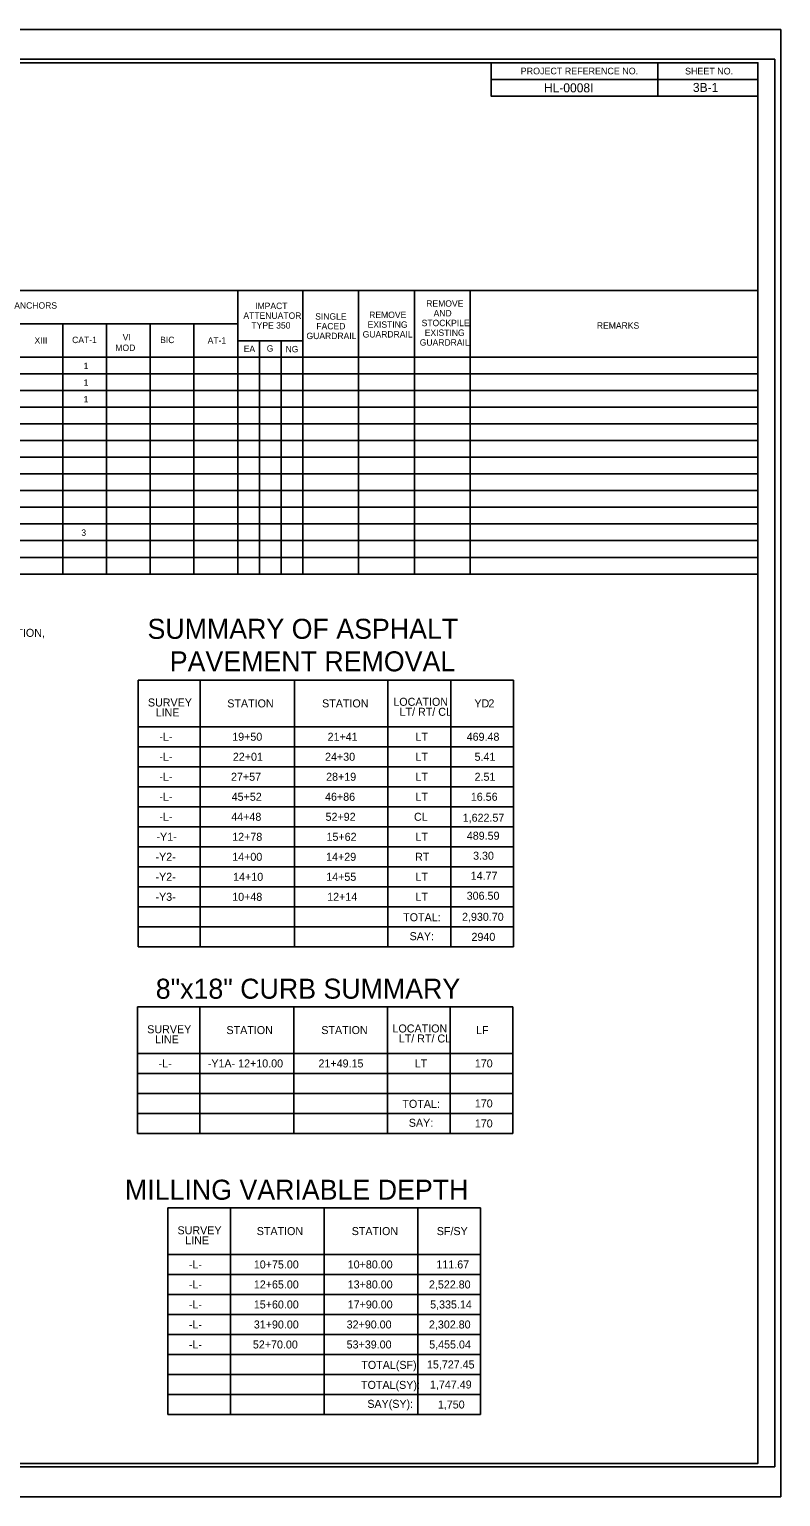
# Model space of a CAD drawing. Extents: x 4059498 to 4061182, y -2958297 to -2957197.
# Drawn here: x 4060619 to 4061182, y -2958297 to -2957197 of the extents above; entities that cross this region are included whole.
import ezdxf

# ---------------------------------------------------------------- set-up
doc = ezdxf.new("R2010")
doc.units = 0
for name, color, linetype in [('Sheet Data Field CELL', 7, 'Continuous'), ('Sheet Plot Border Inside CELL', 7, 'Continuous'), ('Sheet Plot Border Outside CELL', 7, 'Continuous'), ('Sheet Summary Combination CELL', 7, 'Continuous'), ('Sheet Summary Combination Grid CELL', 7, 'Continuous')]:
    doc.layers.add(name, color=color, linetype=linetype)

msp = doc.modelspace()

# ---------------------------------------------------------------- linework, layer by layer
at = {"layer": 'Sheet Plot Border Inside CELL'}
msp.add_lwpolyline([(4061178, -2957219.4), (4059511.5, -2957219.4), (4059511.5, -2958274.5), (4061178, -2958274.5)], close=True, dxfattribs=at)
at = {"layer": 'Sheet Plot Border Outside CELL'}
msp.add_lwpolyline([(4061182.5, -2957197), (4059498.5, -2957197), (4059498.5, -2958297), (4061182.5, -2958297)], close=True, dxfattribs=at)
at = {"layer": 'Sheet Summary Combination CELL'}
for p, q in [((4061090.5, -2957222), (4061090.5, -2957247)), ((4060965.4, -2957234.5), (4061165.5, -2957234.5)), ((4060965.4, -2957247), (4061165.5, -2957247)), ((4060842.1, -2957684.8), (4060842.1, -2957684.8)), ((4060848.3, -2957684.9), (4060848.3, -2957684.9)), ((4060857.4, -2957684.7), (4060857.4, -2957684.7)), ((4060863, -2957684.8), (4060863, -2957684.8)), ((4060841.5, -2957929.8), (4060841.5, -2957929.8)), ((4060847.7, -2957929.9), (4060847.7, -2957929.9)), ((4060856.8, -2957929.7), (4060856.8, -2957929.7)), ((4060862.4, -2957929.8), (4060862.4, -2957929.8)), ((4060864.2, -2958080.5), (4060864.2, -2958080.5)), ((4060870.5, -2958080.6), (4060870.5, -2958080.6)), ((4060879.5, -2958080.4), (4060879.5, -2958080.4)), ((4060885.1, -2958080.5), (4060885.1, -2958080.5))]:
    msp.add_line(p, q, dxfattribs=at)
for points in [[(4061165.5, -2957222), (4059665.5, -2957222), (4059665.5, -2958272), (4061165.5, -2958272)], [(4060965.4, -2957222), (4061165.5, -2957222), (4061165.5, -2957247), (4060965.4, -2957247)]]:
    msp.add_lwpolyline(points, close=True, dxfattribs=at)
at = {"layer": 'Sheet Summary Combination Grid CELL'}
for p, q in [((4059665.5, -2957392.8), (4061165.5, -2957392.8)), ((4060775.4, -2957392.8), (4060775.4, -2957605.3)), ((4060824.3, -2957392.8), (4060824.3, -2957605.3)), ((4060866.1, -2957392.8), (4060866.1, -2957605.3)), ((4060907.9, -2957392.8), (4060907.9, -2957605.3)), ((4060949.7, -2957392.8), (4060949.7, -2957605.3)), ((4060775.4, -2957417.8), (4060298.3, -2957417.8)), ((4060644.2, -2957417.8), (4060644.2, -2957605.3)), ((4060677, -2957417.8), (4060677, -2957605.3)), ((4060709.8, -2957417.8), (4060709.8, -2957605.3)), ((4060742.6, -2957417.8), (4060742.6, -2957605.3)), ((4060775.4, -2957430.5), (4060824, -2957430.5)), ((4060791.7, -2957430.5), (4060791.8, -2957605.3)), ((4060808, -2957430.5), (4060808.1, -2957605.3)), ((4059665.5, -2957442.8), (4061165.5, -2957442.8)), ((4059665.5, -2957455.3), (4061165.5, -2957455.3)), ((4059665.5, -2957467.8), (4061165.5, -2957467.8)), ((4059665.5, -2957480.3), (4061165.5, -2957480.3)), ((4059665.5, -2957492.8), (4061165.5, -2957492.8)), ((4059665.5, -2957505.3), (4061165.5, -2957505.3)), ((4059665.5, -2957517.8), (4061165.5, -2957517.8)), ((4059665.5, -2957530.3), (4061165.5, -2957530.3)), ((4059665.5, -2957542.8), (4061165.5, -2957542.8)), ((4059665.5, -2957555.3), (4061165.5, -2957555.3)), ((4059665.5, -2957567.8), (4061165.5, -2957567.8)), ((4059665.5, -2957580.3), (4061165.5, -2957580.3)), ((4059665.5, -2957592.8), (4061165.5, -2957592.8)), ((4059665.5, -2957605.3), (4061165.5, -2957605.3)), ((4060700.8, -2957684.8), (4060982.2, -2957684.8)), ((4060700.8, -2957684.8), (4060700.8, -2957884.8)), ((4060747.4, -2957684.8), (4060747.4, -2957884.8)), ((4060818.1, -2957684.8), (4060818.1, -2957884.8)), ((4060888.1, -2957684.8), (4060888.1, -2957884.8)), ((4060935.3, -2957684.8), (4060935.3, -2957884.8)), ((4060982.2, -2957684.8), (4060982.2, -2957884.8)), ((4060700.8, -2957719.8), (4060982.2, -2957719.8)), ((4060700.8, -2957734.8), (4060982.2, -2957734.8)), ((4060700.8, -2957749.8), (4060982.2, -2957749.8)), ((4060700.8, -2957764.8), (4060982.2, -2957764.8)), ((4060982.2, -2957764.8), (4060982.2, -2957884.8)), ((4060700.8, -2957779.8), (4060982.2, -2957779.8)), ((4060700.8, -2957794.8), (4060982.2, -2957794.8)), ((4060700.8, -2957794.8), (4060982.2, -2957794.8)), ((4060700.8, -2957809.8), (4060982.2, -2957809.8)), ((4060700.8, -2957824.8), (4060982.2, -2957824.8)), ((4060700.8, -2957839.8), (4060982.2, -2957839.8)), ((4060700.8, -2957854.8), (4060982.2, -2957854.8)), ((4060700.8, -2957869.8), (4060982.2, -2957869.8)), ((4060700.8, -2957884.8), (4060982.2, -2957884.8)), ((4060700.2, -2957929.7), (4060981.6, -2957929.7)), ((4060700.2, -2957929.7), (4060700.2, -2958024.7)), ((4060747.1, -2957929.7), (4060747.1, -2958024.7)), ((4060817.5, -2957929.7), (4060817.5, -2958024.7)), ((4060887.8, -2957929.7), (4060887.8, -2958024.7)), ((4060934.7, -2957929.7), (4060934.7, -2958024.7)), ((4060981.6, -2957929.7), (4060981.6, -2958024.7)), ((4060700.2, -2957964.7), (4060981.6, -2957964.7)), ((4060700.2, -2957979.7), (4060981.6, -2957979.7)), ((4060700.2, -2957994.7), (4060981.6, -2957994.7)), ((4060700.2, -2957994.7), (4060981.6, -2957994.7)), ((4060700.2, -2958009.7), (4060981.6, -2958009.7)), ((4060700.2, -2958024.7), (4060981.6, -2958024.7)), ((4060723, -2958080.4), (4060957.4, -2958080.4)), ((4060723, -2958080.4), (4060723, -2958235.4)), ((4060769.9, -2958080.4), (4060769.9, -2958235.4)), ((4060840.2, -2958080.4), (4060840.2, -2958235.4)), ((4060910.5, -2958080.4), (4060910.5, -2958235.4)), ((4060957.4, -2958080.4), (4060957.4, -2958235.4)), ((4060723, -2958115.4), (4060957.4, -2958115.4)), ((4060723, -2958130.4), (4060957.4, -2958130.4)), ((4060723, -2958145.4), (4060957.4, -2958145.4)), ((4060723, -2958145.4), (4060957.4, -2958145.4)), ((4060723, -2958160.4), (4060957.4, -2958160.4)), ((4060723, -2958160.4), (4060957.4, -2958160.4)), ((4060723, -2958175.4), (4060957.4, -2958175.4)), ((4060723, -2958175.4), (4060957.4, -2958175.4)), ((4060723, -2958190.4), (4060957.4, -2958190.4)), ((4060723, -2958190.4), (4060957.4, -2958190.4)), ((4060723, -2958205.4), (4060957.4, -2958205.4)), ((4060723, -2958205.4), (4060957.4, -2958205.4)), ((4060723, -2958220.4), (4060957.4, -2958220.4)), ((4060723, -2958235.4), (4060957.4, -2958235.4))]:
    msp.add_line(p, q, dxfattribs=at)

# ---------------------------------------------------------------- texts
at = {"layer": 'Sheet Data Field CELL'}
for s, p in [('HL-0008I', (4061005, -2957244.2)), ('3B-1', (4061116.7, -2957243.9))]:
    msp.add_text(s, height=6.75, dxfattribs=at).set_placement(p)
at = {"layer": 'Sheet Summary Combination CELL'}
for s, height, p in [('PROJECT REFERENCE NO.', 5, (4060987.6, -2957230.7)), ('SHEET NO.', 5, (4061110.8, -2957230.8)), ('ANCHORS', 4.8, (4060607.9, -2957406.4)), ('IMPACT', 4.8, (4060788.5, -2957406.7)), ('REMOVE', 4.8, (4060916.8, -2957404.9)), ('ATTENUATOR', 4.8, (4060779.7, -2957414)), ('SINGLE', 4.8, (4060833.5, -2957414.6)), ('EXISTING', 4.8, (4060872.8, -2957420.7)), ('REMOVE', 4.8, (4060874, -2957413.4)), ('STOCKPILE', 4.8, (4060913.3, -2957419.5)), ('AND', 4.8, (4060922.3, -2957412.2)), ('VI', 4.8, (4060689.2, -2957430.2)), ('TYPE 350', 4.8, (4060785.7, -2957421.3)), ('GUARDRAIL', 4.8, (4060827, -2957429.2)), ('FACED', 4.8, (4060834.4, -2957421.9)), ('GUARDRAIL', 4.8, (4060869.1, -2957428)), ('EXISTING', 4.8, (4060915.6, -2957426.8)), ('REMARKS', 4.8, (4061044.7, -2957421.4)), ('XIII', 4.8, (4060623.1, -2957432.6)), ('CAT-1', 4.8, (4060651.3, -2957432.2)), ('MOD', 4.8, (4060683.7, -2957438.1)), ('BIC', 4.8, (4060717.3, -2957432.2)), ('AT-1', 4.8, (4060752.9, -2957432.6)), ('EA', 4.8, (4060779.9, -2957438.9)), ('G', 4.8, (4060797.2, -2957438.6)), ('NG', 4.8, (4060811.3, -2957439.1)), ('GUARDRAIL', 4.8, (4060911.9, -2957434.1)), ('1', 4.8, (4060659.9, -2957451.7)), ('1', 4.8, (4060659.9, -2957464.2)), ('1', 4.8, (4060659.9, -2957476.7)), ('3', 4.8, (4060658.2, -2957576.7)), ('NOTE: APPROXIMATE QUANTITIES ONLY. UNCLASSIFIED EXCAVATION,', 6, (4060352.7, -2957652.4)), ('SURVEY', 6, (4060708.1, -2957704.6)), ('STATION', 6, (4060767.6, -2957705.3)), ('STATION', 6, (4060838.7, -2957705.3)), ('LOCATION', 6, (4060892.1, -2957704.1)), ('LINE', 6, (4060713.9, -2957712.1)), ('LT/ RT/ CL', 6, (4060896.8, -2957711.6)), ('-L-', 6, (4060716.7, -2957730.3)), ('19+50', 6, (4060771.3, -2957730.3)), ('21+41', 6, (4060842.8, -2957730.3)), ('LT', 6, (4060908.7, -2957730.3)), ('469.48', 6, (4060947.1, -2957730.3)), ('-L-', 6, (4060716.7, -2957745.3)), ('22+01', 6, (4060771.8, -2957745.3)), ('24+30', 6, (4060840.9, -2957745.3)), ('LT', 6, (4060908.7, -2957745.3)), ('5.41', 6, (4060953, -2957745.3)), ('-L-', 6, (4060716.7, -2957760.3)), ('27+57', 6, (4060770.4, -2957760.3)), ('28+19', 6, (4060841.7, -2957760.3)), ('LT', 6, (4060908.7, -2957760.3)), ('2.51', 6, (4060953, -2957760.3)), ('-L-', 6, (4060716.7, -2957775.3)), ('45+52', 6, (4060770.9, -2957775.3)), ('46+86', 6, (4060840.9, -2957775.3)), ('LT', 6, (4060908.7, -2957775.3)), ('16.56', 6, (4060950.2, -2957775.3)), ('-L-', 6, (4060716.7, -2957790.3)), ('44+48', 6, (4060770.6, -2957790.3)), ('52+92', 6, (4060841.3, -2957790.3)), ('CL', 6, (4060907.6, -2957790.3)), ('1,622.57', 6, (4060944.1, -2957791)), ('-Y1-', 6, (4060714.5, -2957805.3)), ('12+78', 6, (4060771.3, -2957805.3)), ('15+62', 6, (4060842, -2957805.3)), ('LT', 6, (4060908.7, -2957805.3)), ('489.59', 6, (4060947.2, -2957804.5)), ('-Y2-', 6, (4060713.8, -2957820.3)), ('14+00', 6, (4060771.3, -2957820.3)), ('14+29', 6, (4060841.7, -2957820.3)), ('RT', 6, (4060908.4, -2957820.3)), ('3.30', 6, (4060951.9, -2957819.5)), ('-Y2-', 6, (4060713.8, -2957835.3)), ('14+10', 6, (4060772, -2957835.3)), ('14+55', 6, (4060841.8, -2957835.3)), ('LT', 6, (4060908.7, -2957835.3)), ('14.77', 6, (4060950.1, -2957834.5)), ('-Y3-', 6, (4060713.8, -2957850.3)), ('10+48', 6, (4060771.3, -2957850.3)), ('12+14', 6, (4060842.5, -2957850.3)), ('LT', 6, (4060908.7, -2957850.3)), ('306.50', 6, (4060947.1, -2957849.5)), ('TOTAL:', 6, (4060899.5, -2957865.6)), ('2,930.70', 6, (4060943.6, -2957865.3)), ('SAY:', 6, (4060904.3, -2957879.8)), ('2940', 6, (4060950.7, -2957880.3)), ('SURVEY', 6, (4060707.6, -2957949.6)), ('LOCATION', 6, (4060891.5, -2957949)), ('LINE', 6, (4060713.4, -2957957.1)), ('STATION', 6, (4060767, -2957950.2)), ('STATION', 6, (4060838.1, -2957950.2)), ('LT/ RT/ CL', 6, (4060896.2, -2957956.5)), ('-L-', 6, (4060716.1, -2957975.2)), ('-Y1A- 12+10.00', 6, (4060753, -2957975.2)), ('21+49.15', 6, (4060836, -2957975.2)), ('LT', 6, (4060908.1, -2957975.2)), ('170', 6, (4060953.2, -2957975.2)), ('TOTAL:', 6, (4060898.9, -2958005.5)), ('170', 6, (4060953.2, -2958005.2)), ('SAY:', 6, (4060903.7, -2958019.7)), ('170', 6, (4060953.2, -2958020.2)), ('SURVEY', 6, (4060730.3, -2958100.3)), ('STATION', 6, (4060789.7, -2958100.9)), ('STATION', 6, (4060860.9, -2958100.9)), ('LINE', 6, (4060736.1, -2958107.8)), ('-L-', 6, (4060738.8, -2958125.9)), ('10+75.00', 6, (4060787.5, -2958125.9)), ('10+80.00', 6, (4060857.9, -2958125.9)), ('111.67', 6, (4060924.4, -2958125.9)), ('-L-', 6, (4060738.8, -2958140.9)), ('12+65.00', 6, (4060787.5, -2958140.9)), ('13+80.00', 6, (4060857.9, -2958140.9)), ('2,522.80', 6, (4060918.8, -2958140.9)), ('-L-', 6, (4060738.8, -2958155.9)), ('15+60.00', 6, (4060787.5, -2958155.9)), ('17+90.00', 6, (4060857.9, -2958155.9)), ('5,335.14', 6, (4060919.7, -2958155.9)), ('-L-', 6, (4060738.8, -2958170.9)), ('31+90.00', 6, (4060787.5, -2958170.9)), ('32+90.00', 6, (4060857.1, -2958170.9)), ('2,302.80', 6, (4060918.8, -2958170.9)), ('-L-', 6, (4060738.8, -2958185.9)), ('52+70.00', 6, (4060786.8, -2958185.9)), ('53+39.00', 6, (4060857.1, -2958185.9)), ('5,455.04', 6, (4060919, -2958185.9)), ('TOTAL(SF):', 6, (4060868.1, -2958201.2)), ('15,727.45', 6, (4060917.3, -2958200.9)), ('TOTAL(SY):', 6, (4060867.9, -2958216.2)), ('1,747.49', 6, (4060919.6, -2958215.9)), ('SAY(SY):', 6, (4060872.6, -2958230.4)), ('1,750', 6, (4060925.5, -2958230.9))]:
    msp.add_text(s, height=height, dxfattribs=at).set_placement(p)
for s, p in [('SUMMARY OF ASPHALT', (4060707.8, -2957653.9)), ('PAVEMENT REMOVAL ', (4060724.5, -2957678.3)), ('8"x18" CURB SUMMARY', (4060714, -2957923.7)), ('MILLING VARIABLE DEPTH', (4060690.9, -2958074.4))]:
    msp.add_text(s, height=15, rotation=0.0119, dxfattribs=at).set_placement(p)
at = {"layer": 'Sheet Summary Combination Grid CELL'}
for s, p in [('YD', (4060952.9, -2957705.3)), ('2', (4060963.4, -2957705.3)), ('LF', (4060954.1, -2957950.2)), ('SF/SY', (4060924.7, -2958100.9))]:
    msp.add_text(s, height=6, dxfattribs=at).set_placement(p)

doc.saveas('drawing.dxf')
